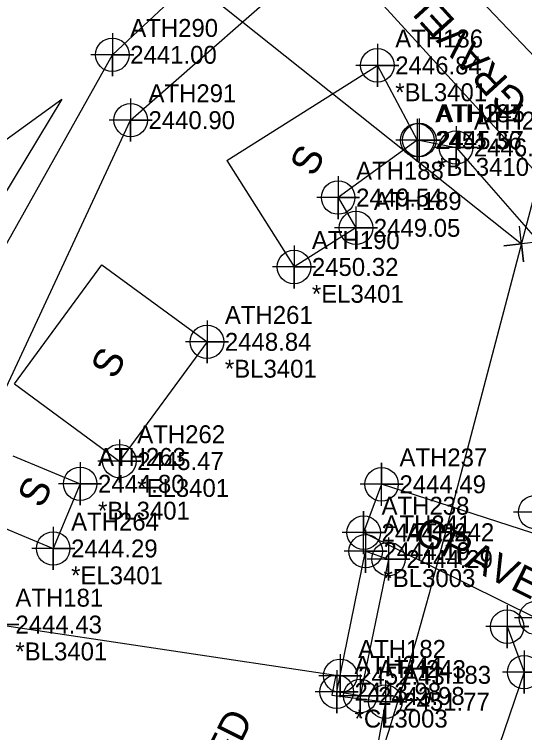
# Model space of a CAD drawing. Extents: x 983976 to 986421, y 758828 to 761458.
# Drawn here: x 984833.7 to 984904.9, y 760270.5 to 760370.7 of the extents above; entities that cross this region are included whole.
import ezdxf

# ---------------------------------------------------------------- set-up
doc = ezdxf.new("R2010")
doc.units = 0
for name, color, linetype in [('COGO Default Chain', 7, 'Continuous'), ('COGO Default Curve', 7, 'Continuous'), ('CTL Secondary Horizontal and Vertical Leader', 7, 'Continuous'), ('CTL Secondary Horizontal and Vertical Text', 7, 'Continuous'), ('Exist Building', 7, 'Continuous'), ('Exist Building Text', 7, 'Continuous'), ('Exist DTM Crownline', 7, 'Continuous'), ('Exist Horizontal Alignment', 7, 'Continuous'), ('Exist Hydro Jurisdictional Stream or Body of Water', 7, 'Continuous'), ('Exist Other Culture Fence Line', 7, 'Continuous'), ('Exist Other Culture Fence Line Cogo Comment', 7, 'Continuous'), ('Exist Other Culture Fence Line Cogo Elevation', 7, 'Continuous'), ('Exist Other Culture Fence Line Cogo Number', 7, 'Continuous'), ('Exist Other Culture Fence Line Cogo Point CELL', 7, 'Continuous'), ('Exist Property Corner CELL', 7, 'Continuous'), ('Exist Property Line', 7, 'Continuous'), ('Exist Right of Way Line', 7, 'Continuous'), ('Exist Roads EOP', 7, 'Continuous'), ('Exist Roads EOP Other', 7, 'Continuous'), ('Exist Roads EOP Other Cogo Comment', 7, 'Continuous'), ('Exist Roads EOP Other Cogo Elevation', 7, 'Continuous'), ('Exist Roads EOP Other Cogo Number', 7, 'Continuous'), ('Exist Roads EOP Other Cogo Point CELL', 7, 'Continuous'), ('Exist Roads Soil', 7, 'Continuous'), ('Exist Roads Soil Cogo Elevation', 7, 'Continuous'), ('Exist Roads Soil Cogo Number', 7, 'Continuous'), ('Exist Roads Soil Cogo Point CELL', 7, 'Continuous'), ('Exist Roads Soil Text', 7, 'Continuous'), ('Exist Structure Major Bridge WW Cogo Point CELL', 7, 'Continuous'), ('Exist Utilities Power Transformer CELL', 7, 'Continuous'), ('Exist Vegetation Hedge Row', 7, 'Continuous')]:
    doc.layers.add(name, color=color, linetype=linetype)

msp = doc.modelspace()

# ---------------------------------------------------------------- linework, layer by layer
at = {"layer": 'COGO Default Chain'}
msp.add_arc((984418.15, 760419.36), 520.87, 328.4601, 345.2561, dxfattribs=at)
at = {"layer": 'COGO Default Curve'}
msp.add_arc((984418.15, 760419.36), 520.87, 328.4601, 345.2561, dxfattribs=at)
at = {"layer": 'Exist Building'}
for p, q in [((984863.35, 760350.33), (984884.37, 760363.6)), ((984863.35, 760350.33), (984872.73, 760335.46)), ((984833.68, 760319.14), (984845.91, 760335.78)), ((984845.91, 760335.78), (984860.58, 760325.01)), ((984860.58, 760325.01), (984848.34, 760308.36)), ((984833.68, 760319.14), (984848.34, 760308.36)), ((984833.45, 760309.11), (984842.86, 760305.19)), ((984842.86, 760305.19), (984839.1, 760296.16)), ((984829.69, 760300.08), (984839.1, 760296.16)), ((984878.57, 760278.48), (984878.02, 760275.7)), ((984878.02, 760275.7), (984885.49, 760274.77))]:
    msp.add_line(p, q, dxfattribs=at)
for points in [[(984884.37, 760363.6), (984889.95, 760353.16), (984878.9, 760345.15), (984881.38, 760340.92), (984872.73, 760335.46)], [(984831.32, 760285.54), (984878.57, 760278.48)], [(984885.49, 760274.77), (984880.79, 760249.02), (984872.14, 760250.36)]]:
    msp.add_lwpolyline(points, dxfattribs=at)
at = {"layer": 'Exist Horizontal Alignment'}
msp.add_arc((984418.15, 760419.36), 520.87, 328.4601, 345.2561, dxfattribs=at)
at = {"layer": 'Exist Hydro Jurisdictional Stream or Body of Water'}
for points in [[(984827.07, 760112.31), (984826.36, 760116.65), (984820.04, 760157.78), (984809.83, 760195.88), (984798.99, 760237.51), (984800.74, 760260.98), (984804.2, 760288.2), (984847.36, 760365.08), (984869.62, 760385.92), (984871.86, 760387.27)], [(984833.78, 760122.6), (984833.36, 760124.9), (984829.26, 760164.03), (984817.97, 760198), (984808.33, 760238.74), (984808.9, 760259.21), (984814.88, 760280.8), (984849.91, 760355.96), (984876.59, 760379.37), (984877.56, 760380.02)]]:
    msp.add_lwpolyline(points, dxfattribs=at)
at = {"layer": 'Exist Other Culture Fence Line'}
for points in [[(984890.23, 760353.18), (984895.36, 760352.14), (984912.01, 760333.14), (984906.41, 760301.23)], [(984902.51, 760285.25), (984904.87, 760278.9), (984890.36, 760236.31), (984870.51, 760197.95), (984840.66, 760148.02), (984831.85, 760170.26)]]:
    msp.add_lwpolyline(points, dxfattribs=at)
at = {"layer": 'Exist Other Culture Fence Line Cogo Point CELL'}
for points in [[(984890.23, 760356.18), (984890.23, 760350.18), (984890.23, 760353.18), (984893.23, 760353.18), (984887.23, 760353.18)], [(984895.36, 760355.14), (984895.36, 760349.14), (984895.36, 760352.14), (984898.36, 760352.14), (984892.36, 760352.14)], [(984906.41, 760304.23), (984906.41, 760298.23), (984906.41, 760301.23), (984909.41, 760301.23), (984903.41, 760301.23)], [(984902.51, 760288.25), (984902.51, 760282.25), (984902.51, 760285.25), (984905.51, 760285.25), (984899.51, 760285.25)], [(984904.87, 760281.9), (984904.87, 760275.9), (984904.87, 760278.9), (984907.87, 760278.9), (984901.87, 760278.9)]]:
    msp.add_lwpolyline(points, dxfattribs=at)
for centre in [(984890.23, 760353.18), (984895.36, 760352.14), (984906.41, 760301.23), (984902.51, 760285.25), (984904.87, 760278.9)]:
    msp.add_circle(centre, 2.34, dxfattribs=at)
at = {"layer": 'Exist Property Corner CELL'}
msp.add_line((984904.5, 760338.69), (984904.5, 760338.69), dxfattribs=at)
msp.add_lwpolyline([(984906.99, 760338.97), (984902.02, 760338.41), (984904.5, 760338.69), (984904.78, 760336.2), (984904.22, 760341.17)], dxfattribs=at)
at = {"layer": 'Exist Property Line'}
msp.add_line((984798.29, 760423.21), (984904.5, 760338.69), dxfattribs=at)
at = {"layer": 'Exist Right of Way Line'}
msp.add_line((984892.86, 760294.44), (984907.36, 760349.55), dxfattribs=at)
msp.add_arc((984418.15, 760419.36), 490.87, 328.4601, 345.2561, dxfattribs=at)
at = {"layer": 'Exist Roads EOP'}
for points in [[(984848.52, 760141.85), (984870.29, 760181.25), (984890.88, 760222.66), (984906.2, 760265.41), (984918.1, 760309.21)], [(984863.71, 760131.91), (984886.81, 760172.15), (984906.97, 760214.22), (984924.47, 760259.67), (984936.56, 760305.94)]]:
    msp.add_spline(points, degree=3, dxfattribs=at)
at = {"layer": 'Exist Roads EOP Other'}
msp.add_lwpolyline([(984882.73, 760295.78), (984885.93, 760294.68), (984881.98, 760275.57), (984878.69, 760276.16), (984882.73, 760295.78)], dxfattribs=at)
at = {"layer": 'Exist Roads EOP Other Cogo Point CELL'}
for points in [[(984882.73, 760298.78), (984882.73, 760292.78), (984882.73, 760295.78), (984885.73, 760295.78), (984879.73, 760295.78)], [(984885.93, 760297.68), (984885.93, 760291.68), (984885.93, 760294.68), (984888.93, 760294.68), (984882.93, 760294.68)], [(984878.69, 760279.16), (984878.69, 760273.16), (984878.69, 760276.16), (984881.69, 760276.16), (984875.69, 760276.16)], [(984881.98, 760278.57), (984881.98, 760272.57), (984881.98, 760275.57), (984884.98, 760275.57), (984878.98, 760275.57)]]:
    msp.add_lwpolyline(points, dxfattribs=at)
for centre in [(984882.73, 760295.78), (984885.93, 760294.68), (984878.69, 760276.16), (984881.98, 760275.57)]:
    msp.add_circle(centre, 2.34, dxfattribs=at)
at = {"layer": 'Exist Roads Soil'}
for points in [[(984888.43, 760383.6), (984916.85, 760353.77), (984928.05, 760348.28)], [(984880.25, 760377.45), (984910.62, 760344.22), (984921.28, 760322.4)], [(984916.5, 760303.32), (984909.23, 760297.26), (984884.96, 760305.12), (984882.46, 760298.38), (984906.51, 760286.47), (984909.05, 760275.88)]]:
    msp.add_lwpolyline(points, dxfattribs=at)
at = {"layer": 'Exist Roads Soil Cogo Point CELL'}
for points in [[(984884.96, 760302.12), (984884.96, 760308.12), (984884.96, 760305.12), (984887.96, 760305.12), (984881.96, 760305.12)], [(984882.46, 760295.38), (984882.46, 760301.38), (984882.46, 760298.38), (984885.46, 760298.38), (984879.46, 760298.38)], [(984906.51, 760283.47), (984906.51, 760289.47), (984906.51, 760286.47), (984909.51, 760286.47), (984903.51, 760286.47)]]:
    msp.add_lwpolyline(points, dxfattribs=at)
for centre in [(984884.96, 760305.12), (984882.46, 760298.38), (984906.51, 760286.47)]:
    msp.add_circle(centre, 2.34, dxfattribs=at)
at = {"layer": 'Exist Structure Major Bridge WW Cogo Point CELL'}
for points in [[(984884.37, 760366.6), (984884.37, 760360.6), (984884.37, 760363.6), (984887.37, 760363.6), (984881.37, 760363.6)], [(984889.95, 760356.16), (984889.95, 760350.16), (984889.95, 760353.16), (984892.95, 760353.16), (984886.95, 760353.16)], [(984878.9, 760348.15), (984878.9, 760342.15), (984878.9, 760345.15), (984881.9, 760345.15), (984875.9, 760345.15)], [(984881.38, 760343.92), (984881.38, 760337.92), (984881.38, 760340.92), (984884.38, 760340.92), (984878.38, 760340.92)], [(984872.73, 760338.46), (984872.73, 760332.46), (984872.73, 760335.46), (984875.73, 760335.46), (984869.73, 760335.46)], [(984860.58, 760328.01), (984860.58, 760322.01), (984860.58, 760325.01), (984863.58, 760325.01), (984857.58, 760325.01)], [(984848.34, 760311.36), (984848.34, 760305.36), (984848.34, 760308.36), (984851.34, 760308.36), (984845.34, 760308.36)], [(984842.86, 760308.19), (984842.86, 760302.19), (984842.86, 760305.19), (984845.86, 760305.19), (984839.86, 760305.19)], [(984839.1, 760299.16), (984839.1, 760293.16), (984839.1, 760296.16), (984842.1, 760296.16), (984836.1, 760296.16)], [(984831.32, 760288.54), (984831.32, 760282.54), (984831.32, 760285.54), (984834.32, 760285.54), (984828.32, 760285.54)], [(984879.19, 760281.39), (984879.19, 760275.39), (984879.19, 760278.39), (984882.19, 760278.39), (984876.19, 760278.39)], [(984885.49, 760277.77), (984885.49, 760271.77), (984885.49, 760274.77), (984888.49, 760274.77), (984882.49, 760274.77)]]:
    msp.add_lwpolyline(points, dxfattribs=at)
for centre in [(984884.37, 760363.6), (984889.95, 760353.16), (984878.9, 760345.15), (984881.38, 760340.92), (984872.73, 760335.46), (984860.58, 760325.01), (984848.34, 760308.36), (984842.86, 760305.19), (984839.1, 760296.16), (984879.19, 760278.39), (984885.49, 760274.77)]:
    msp.add_circle(centre, 2.34, dxfattribs=at)
at = {"layer": 'Exist Utilities Power Transformer CELL'}
for points in [[(984847.36, 760368.08), (984847.36, 760362.08), (984847.36, 760365.08), (984850.36, 760365.08), (984844.36, 760365.08)], [(984849.91, 760358.96), (984849.91, 760352.96), (984849.91, 760355.96), (984852.91, 760355.96), (984846.91, 760355.96)]]:
    msp.add_lwpolyline(points, dxfattribs=at)
for centre in [(984847.36, 760365.08), (984849.91, 760355.96)]:
    msp.add_circle(centre, 2.34, dxfattribs=at)
at = {"layer": 'Exist Vegetation Hedge Row'}
msp.add_lwpolyline([(984803.22, 760209.05), (984816.06, 760156.75), (984820.49, 760129.44), (984812.09, 760129.44), (984808.59, 760155.58), (984801.59, 760193.64), (984792.48, 760228), (984788.01, 760269.97), (984797.85, 760304.14), (984830.1, 760351.54), (984840.31, 760358.89), (984809.69, 760308.23), (984798.25, 760285.35), (984794.17, 760235.5), (984803.22, 760209.05)], dxfattribs=at)

# ---------------------------------------------------------------- texts
at = {"layer": 'CTL Secondary Horizontal and Vertical Leader'}
for s, p in [('2441.00', (984849.86, 760363.83)), ('2440.90', (984852.41, 760354.71))]:
    msp.add_text(s, height=2.5, dxfattribs=at).set_placement(p)
at = {"layer": 'CTL Secondary Horizontal and Vertical Text'}
for s, p in [('ATH290', (984849.86, 760367.58)), ('ATH291', (984852.41, 760358.46))]:
    msp.add_text(s, height=2.5, dxfattribs=at).set_placement(p)
at = {"layer": 'Exist Building Text'}
for s, rotation, p in [('S', 62.6048, (984875.52, 760347.9)), ('S', 62.6048, (984847.72, 760319.63)), ('S', 62.6048, (984837.47, 760301.62)), ('1SFD', 63.2641, (984860.94, 760260.15))]:
    msp.add_text(s, height=4, rotation=rotation, dxfattribs=at).set_placement(p)
at = {"layer": 'Exist DTM Crownline'}
for s, p in [('2446.84', (984886.87, 760362.35)), ('*BL3401', (984886.87, 760358.6)), ('2451.36', (984892.45, 760351.91)), ('2449.54', (984881.4, 760343.9)), ('2449.05', (984883.88, 760339.67)), ('2450.32', (984875.23, 760334.21)), ('*EL3401', (984875.23, 760330.46)), ('2448.84', (984863.08, 760323.76)), ('*BL3401', (984863.08, 760320.01)), ('2445.47', (984850.84, 760307.11)), ('2444.80', (984845.36, 760303.94)), ('*EL3401', (984850.84, 760303.36)), ('*BL3401', (984845.36, 760300.19)), ('2444.29', (984841.6, 760294.91)), ('*EL3401', (984841.6, 760291.16)), ('2444.43', (984833.82, 760284.29)), ('*BL3401', (984833.82, 760280.54)), ('2452.43', (984881.69, 760277.14)), ('2451.77', (984887.99, 760273.52))]:
    msp.add_text(s, height=2.5, dxfattribs=at).set_placement(p)
at = {"layer": 'Exist Other Culture Fence Line Cogo Comment'}
msp.add_text('*BL3410', height=2.5, dxfattribs=at).set_placement((984892.73, 760348.18))
at = {"layer": 'Exist Other Culture Fence Line Cogo Elevation'}
for s, p in [('2445.57', (984892.73, 760351.93)), ('2446.18', (984897.86, 760350.89))]:
    msp.add_text(s, height=2.5, dxfattribs=at).set_placement(p)
at = {"layer": 'Exist Other Culture Fence Line Cogo Number'}
for s, p in [('ATH245', (984892.73, 760355.68)), ('ATH246', (984897.86, 760354.64))]:
    msp.add_text(s, height=2.5, dxfattribs=at).set_placement(p)
at = {"layer": 'Exist Roads EOP'}
for s, p in [('ATH186', (984886.87, 760366.1)), ('ATH187', (984892.45, 760355.66)), ('ATH188', (984881.4, 760347.65)), ('ATH189', (984883.88, 760343.42)), ('ATH190', (984875.23, 760337.96)), ('ATH261', (984863.08, 760327.51)), ('ATH262', (984850.84, 760310.86)), ('ATH263', (984845.36, 760307.69)), ('ATH264', (984841.6, 760298.66)), ('ATH181', (984833.82, 760288.04)), ('ATH182', (984881.69, 760280.89)), ('ATH183', (984887.99, 760277.27))]:
    msp.add_text(s, height=2.5, dxfattribs=at).set_placement(p)
at = {"layer": 'Exist Roads EOP Other Cogo Comment'}
for s, p in [('*BL3003', (984885.23, 760290.78)), ('*CL3003', (984881.19, 760271.16))]:
    msp.add_text(s, height=2.5, dxfattribs=at).set_placement(p)
at = {"layer": 'Exist Roads EOP Other Cogo Elevation'}
for s, p in [('2444.19', (984885.23, 760294.53)), ('2444.29', (984888.43, 760293.43)), ('2443.98', (984881.19, 760274.91)), ('2443.98', (984884.48, 760274.32))]:
    msp.add_text(s, height=2.5, dxfattribs=at).set_placement(p)
at = {"layer": 'Exist Roads EOP Other Cogo Number'}
for s, p in [('ATH241', (984885.23, 760298.28)), ('ATH242', (984888.43, 760297.18)), ('ATH244', (984881.19, 760278.66)), ('ATH243', (984884.48, 760278.07))]:
    msp.add_text(s, height=2.5, dxfattribs=at).set_placement(p)
at = {"layer": 'Exist Roads Soil Cogo Elevation'}
for s, p in [('2444.49', (984887.46, 760303.87)), ('2444.24', (984884.96, 760297.13))]:
    msp.add_text(s, height=2.5, dxfattribs=at).set_placement(p)
at = {"layer": 'Exist Roads Soil Cogo Number'}
for s, p in [('ATH237', (984887.46, 760307.62)), ('ATH238', (984884.96, 760300.88))]:
    msp.add_text(s, height=2.5, dxfattribs=at).set_placement(p)
at = {"layer": 'Exist Roads Soil Text'}
for rotation, p in [(132.4309, (984905.65, 760358.56)), (333.6517, (984889.2, 760297.28))]:
    msp.add_text('GRAVEL', height=4, rotation=rotation, dxfattribs=at).set_placement(p)

doc.saveas('drawing.dxf')
